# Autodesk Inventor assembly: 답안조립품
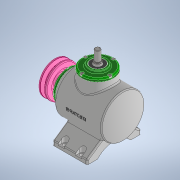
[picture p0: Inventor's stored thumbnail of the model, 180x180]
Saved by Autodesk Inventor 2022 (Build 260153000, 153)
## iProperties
Created: 2023-04
Part Number: 답안조립품
Document SubType Name: Assembly
Designer: Admin
Author: Admin
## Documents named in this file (17)
- C:\Users\Admin\Desktop\730411V1015\답안조립품.iam
- C:\Users\Admin\Desktop\730411V1015\본체.ipt
- C:\Users\Admin\Desktop\730411V1015\커버.ipt
- C:\Users\Admin\Desktop\730411V1015\베어링 6203.ipt
- C:\Users\Admin\Desktop\730411V1015\메인 축.ipt
- 메인 축.ipt
- C:\Users\Admin\Desktop\730411V1015\오일실 17 x 32 x 8.ipt
- C:\Users\Admin\Desktop\730411V1015\키 5 x 5 x 14.ipt
- C:\Users\Admin\Desktop\730411V1015\메인 베벨기어.ipt
- C:\Users\Admin\Desktop\730411V1015\서브 축.ipt
- 서브 축.ipt
- C:\Users\Admin\Desktop\730411V1015\키 4 x 4 x 14.ipt
- C:\Users\Admin\Desktop\730411V1015\서브 베벨기어.ipt
- C:\Users\Admin\Desktop\730411V1015\V-벨트풀리.ipt
- C:\Users\Admin\Desktop\730411V1015\볼트 M4 x 10.ipt
- C:\Users\Admin\Desktop\730411V1015\와셔 4 x 16.ipt
- C:\Users\Admin\Desktop\730411V1015\육각볼트 M4 x 8.ipt
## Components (1 placed, 1 different names)
1. V-벨트풀리:1
